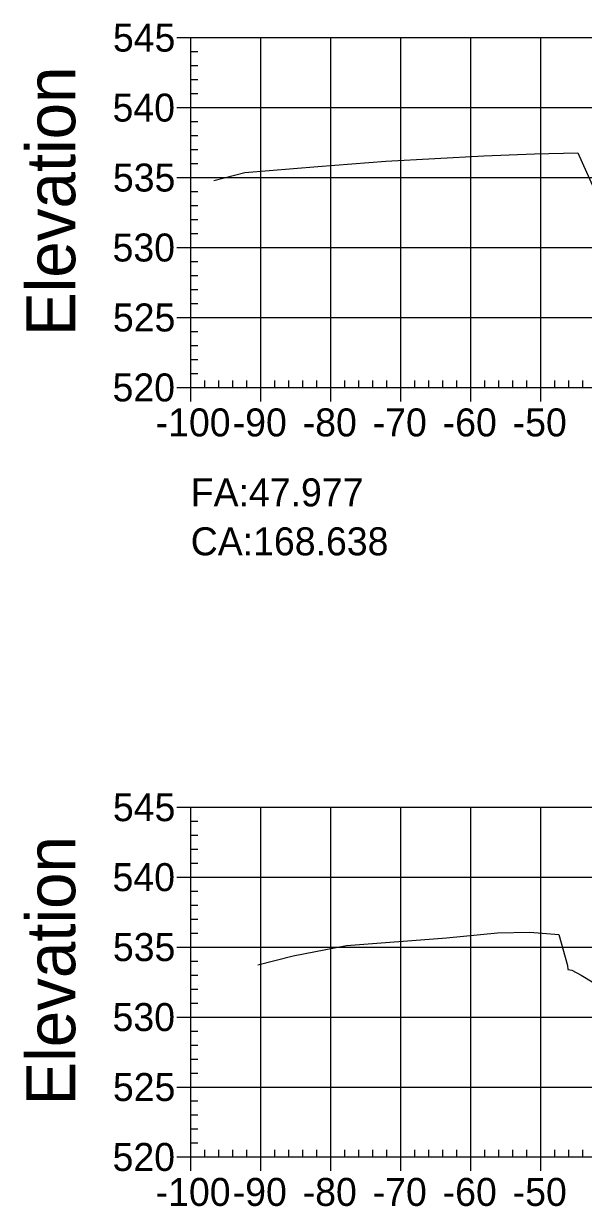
# Model space of a CAD drawing. Extents: x 704834 to 709892, y 372981 to 377533.
# Drawn here: x 705463 to 705543, y 373825.8 to 373994.8 of the extents above; entities that cross this region are included whole.
import ezdxf

# ---------------------------------------------------------------- set-up
doc = ezdxf.new("R2010")
doc.units = 0
for name, color, linetype in [('57', 7, 'Continuous'), ('59', 7, 'Continuous'), ('60', 7, 'Continuous'), ('Existing', 7, 'Continuous')]:
    doc.layers.add(name, color=color, linetype=linetype)

msp = doc.modelspace()

# ---------------------------------------------------------------- linework, layer by layer
at = {"layer": '57'}
for p, q in [((705484.87, 373992.82), (705486.87, 373992.82)), ((705486.87, 373992.82), (705686.87, 373992.82)), ((705486.87, 373942.82), (705486.87, 373992.82)), ((705486.87, 373942.82), (705486.87, 373992.82)), ((705496.87, 373942.82), (705496.87, 373992.82)), ((705506.87, 373942.82), (705506.87, 373992.82)), ((705516.87, 373942.82), (705516.87, 373992.82)), ((705526.87, 373942.82), (705526.87, 373992.82)), ((705536.87, 373942.82), (705536.87, 373992.82)), ((705486.87, 373990.82), (705487.87, 373990.82)), ((705486.87, 373988.82), (705487.87, 373988.82)), ((705486.87, 373986.82), (705487.87, 373986.82)), ((705486.87, 373984.82), (705487.87, 373984.82)), ((705484.87, 373982.82), (705486.87, 373982.82)), ((705486.87, 373982.82), (705686.87, 373982.82)), ((705486.87, 373980.82), (705487.87, 373980.82)), ((705486.87, 373978.82), (705487.87, 373978.82)), ((705486.87, 373976.82), (705487.87, 373976.82)), ((705486.87, 373974.82), (705487.87, 373974.82)), ((705484.87, 373972.82), (705486.87, 373972.82)), ((705486.87, 373972.82), (705686.87, 373972.82)), ((705486.87, 373970.82), (705487.87, 373970.82)), ((705486.87, 373968.82), (705487.87, 373968.82)), ((705486.87, 373966.82), (705487.87, 373966.82)), ((705486.87, 373964.82), (705487.87, 373964.82)), ((705484.87, 373962.82), (705486.87, 373962.82)), ((705486.87, 373962.82), (705686.87, 373962.82)), ((705486.87, 373960.82), (705487.87, 373960.82)), ((705486.87, 373958.82), (705487.87, 373958.82)), ((705486.87, 373956.82), (705487.87, 373956.82)), ((705486.87, 373954.82), (705487.87, 373954.82)), ((705484.87, 373952.82), (705486.87, 373952.82)), ((705486.87, 373952.82), (705686.87, 373952.82)), ((705486.87, 373950.82), (705487.87, 373950.82)), ((705486.87, 373948.82), (705487.87, 373948.82)), ((705486.87, 373946.82), (705487.87, 373946.82)), ((705486.87, 373944.82), (705487.87, 373944.82)), ((705488.87, 373942.82), (705488.87, 373943.82)), ((705490.87, 373942.82), (705490.87, 373943.82)), ((705492.87, 373942.82), (705492.87, 373943.82)), ((705494.87, 373942.82), (705494.87, 373943.82)), ((705498.87, 373942.82), (705498.87, 373943.82)), ((705500.87, 373942.82), (705500.87, 373943.82)), ((705502.87, 373942.82), (705502.87, 373943.82)), ((705504.87, 373942.82), (705504.87, 373943.82)), ((705508.87, 373942.82), (705508.87, 373943.82)), ((705510.87, 373942.82), (705510.87, 373943.82)), ((705512.87, 373942.82), (705512.87, 373943.82)), ((705514.87, 373942.82), (705514.87, 373943.82)), ((705518.87, 373942.82), (705518.87, 373943.82)), ((705520.87, 373942.82), (705520.87, 373943.82)), ((705522.87, 373942.82), (705522.87, 373943.82)), ((705524.87, 373942.82), (705524.87, 373943.82)), ((705528.87, 373942.82), (705528.87, 373943.82)), ((705530.87, 373942.82), (705530.87, 373943.82)), ((705532.87, 373942.82), (705532.87, 373943.82)), ((705534.87, 373942.82), (705534.87, 373943.82)), ((705538.87, 373942.82), (705538.87, 373943.82)), ((705540.87, 373942.82), (705540.87, 373943.82)), ((705542.87, 373942.82), (705542.87, 373943.82)), ((705484.87, 373942.82), (705486.87, 373942.82)), ((705486.87, 373942.82), (705686.87, 373942.82)), ((705486.87, 373942.82), (705686.87, 373942.82)), ((705486.87, 373940.82), (705486.87, 373942.82)), ((705496.87, 373940.82), (705496.87, 373942.82)), ((705506.87, 373940.82), (705506.87, 373942.82)), ((705516.87, 373940.82), (705516.87, 373942.82)), ((705526.87, 373940.82), (705526.87, 373942.82)), ((705536.87, 373940.82), (705536.87, 373942.82)), ((705484.87, 373882.82), (705486.87, 373882.82)), ((705486.87, 373882.82), (705686.87, 373882.82)), ((705486.87, 373832.82), (705486.87, 373882.82)), ((705486.87, 373832.82), (705486.87, 373882.82)), ((705496.87, 373832.82), (705496.87, 373882.82)), ((705506.87, 373832.82), (705506.87, 373882.82)), ((705516.87, 373832.82), (705516.87, 373882.82)), ((705526.87, 373832.82), (705526.87, 373882.82)), ((705536.87, 373832.82), (705536.87, 373882.82)), ((705486.87, 373880.82), (705487.87, 373880.82)), ((705486.87, 373878.82), (705487.87, 373878.82)), ((705486.87, 373876.82), (705487.87, 373876.82)), ((705486.87, 373874.82), (705487.87, 373874.82)), ((705484.87, 373872.82), (705486.87, 373872.82)), ((705486.87, 373872.82), (705686.87, 373872.82)), ((705486.87, 373870.82), (705487.87, 373870.82)), ((705486.87, 373868.82), (705487.87, 373868.82)), ((705486.87, 373866.82), (705487.87, 373866.82)), ((705486.87, 373864.82), (705487.87, 373864.82)), ((705484.87, 373862.82), (705486.87, 373862.82)), ((705486.87, 373862.82), (705686.87, 373862.82)), ((705486.87, 373860.82), (705487.87, 373860.82)), ((705486.87, 373858.82), (705487.87, 373858.82)), ((705486.87, 373856.82), (705487.87, 373856.82)), ((705486.87, 373854.82), (705487.87, 373854.82)), ((705484.87, 373852.82), (705486.87, 373852.82)), ((705486.87, 373852.82), (705686.87, 373852.82)), ((705486.87, 373850.82), (705487.87, 373850.82)), ((705486.87, 373848.82), (705487.87, 373848.82)), ((705486.87, 373846.82), (705487.87, 373846.82)), ((705486.87, 373844.82), (705487.87, 373844.82)), ((705484.87, 373842.82), (705486.87, 373842.82)), ((705486.87, 373842.82), (705686.87, 373842.82)), ((705486.87, 373840.82), (705487.87, 373840.82)), ((705486.87, 373838.82), (705487.87, 373838.82)), ((705486.87, 373836.82), (705487.87, 373836.82)), ((705486.87, 373834.82), (705487.87, 373834.82)), ((705488.87, 373832.82), (705488.87, 373833.82)), ((705490.87, 373832.82), (705490.87, 373833.82)), ((705492.87, 373832.82), (705492.87, 373833.82)), ((705494.87, 373832.82), (705494.87, 373833.82)), ((705498.87, 373832.82), (705498.87, 373833.82)), ((705500.87, 373832.82), (705500.87, 373833.82)), ((705502.87, 373832.82), (705502.87, 373833.82)), ((705504.87, 373832.82), (705504.87, 373833.82)), ((705508.87, 373832.82), (705508.87, 373833.82)), ((705510.87, 373832.82), (705510.87, 373833.82)), ((705512.87, 373832.82), (705512.87, 373833.82)), ((705514.87, 373832.82), (705514.87, 373833.82)), ((705518.87, 373832.82), (705518.87, 373833.82)), ((705520.87, 373832.82), (705520.87, 373833.82)), ((705522.87, 373832.82), (705522.87, 373833.82)), ((705524.87, 373832.82), (705524.87, 373833.82)), ((705528.87, 373832.82), (705528.87, 373833.82)), ((705530.87, 373832.82), (705530.87, 373833.82)), ((705532.87, 373832.82), (705532.87, 373833.82)), ((705534.87, 373832.82), (705534.87, 373833.82)), ((705538.87, 373832.82), (705538.87, 373833.82)), ((705540.87, 373832.82), (705540.87, 373833.82)), ((705542.87, 373832.82), (705542.87, 373833.82)), ((705484.87, 373832.82), (705486.87, 373832.82)), ((705486.87, 373832.82), (705686.87, 373832.82)), ((705486.87, 373832.82), (705686.87, 373832.82)), ((705486.87, 373830.82), (705486.87, 373832.82)), ((705496.87, 373830.82), (705496.87, 373832.82)), ((705506.87, 373830.82), (705506.87, 373832.82)), ((705516.87, 373830.82), (705516.87, 373832.82)), ((705526.87, 373830.82), (705526.87, 373832.82)), ((705536.87, 373830.82), (705536.87, 373832.82))]:
    msp.add_line(p, q, dxfattribs=at)
at = {"layer": 'Existing'}
for points in [[(705490.15, 373972.39), (705494.6, 373973.55), (705505.05, 373974.39), (705514.77, 373975.16), (705528.75, 373975.94), (705535.98, 373976.19), (705542.18, 373976.33), (705544.48, 373971.25)], [(705496.45, 373860.27), (705501.52, 373861.56), (705509.14, 373863.05), (705523.43, 373864.15), (705530.68, 373864.88), (705535.31, 373864.94), (705539.45, 373864.64), (705540.68, 373860.21), (705540.76, 373859.64), (705541.3, 373859.52), (705542.67, 373858.81), (705546.51, 373856.46)]]:
    msp.add_lwpolyline(points, dxfattribs=at)

# ---------------------------------------------------------------- texts
msp.add_text('CA:168.638', height=4).set_placement((705486.87, 373918.82))
at = {"layer": '57'}
for s, p in [('545', (705475.75, 373990.82)), ('540', (705475.7, 373980.82)), ('535', (705475.75, 373970.82)), ('530', (705475.7, 373960.82)), ('525', (705475.75, 373950.82)), ('520', (705475.7, 373940.82)), ('-100', (705481.86, 373935.82)), ('-90', (705492.87, 373935.82)), ('-80', (705502.87, 373935.82)), ('-70', (705512.87, 373935.82)), ('-60', (705522.87, 373935.82)), ('-50', (705532.87, 373935.82)), ('545', (705475.75, 373880.82)), ('540', (705475.7, 373870.82)), ('535', (705475.75, 373860.82)), ('530', (705475.7, 373850.82)), ('525', (705475.75, 373840.82)), ('520', (705475.7, 373830.82)), ('-100', (705481.86, 373825.82)), ('-90', (705492.87, 373825.82)), ('-80', (705502.87, 373825.82)), ('-70', (705512.87, 373825.82)), ('-60', (705522.87, 373825.82)), ('-50', (705532.87, 373825.82))]:
    msp.add_text(s, height=4, dxfattribs=at).set_placement(p)
at = {"layer": '59'}
msp.add_text('FA:47.977', height=4, dxfattribs=at).set_placement((705486.87, 373925.82))
at = {"layer": '60'}
for p in [(705470.37, 373950.18), (705470.37, 373840.18)]:
    msp.add_text('Elevation', height=7, rotation=90, dxfattribs=at).set_placement(p)

doc.saveas('drawing.dxf')
